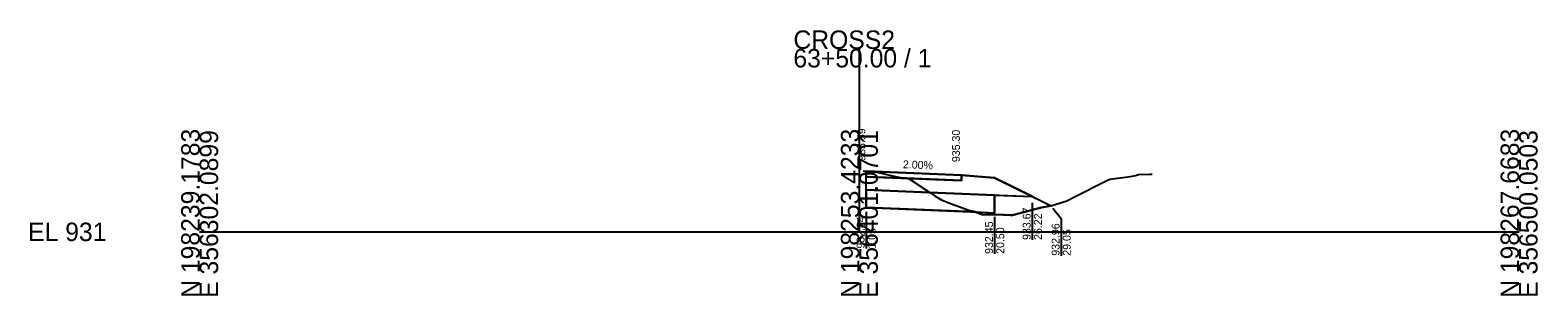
# Model space of a CAD drawing. Extents: x -26 to 203, y -10 to 14021.
# Drawn here: x -25.7 to 202.8, y 4490.3 to 4530.5 of the extents above; entities that cross this region are included whole.
import ezdxf

# ---------------------------------------------------------------- set-up
doc = ezdxf.new("R2010")
doc.units = 0
for name, color, linetype in [('Default', 7, 'Continuous'), ('P_E_XS_Ground', 7, 'Continuous'), ('P_XS', 7, 'Continuous'), ('P_XS_EAR_CommonGrnd', 7, 'Continuous'), ('P_XS_Lane', 7, 'Continuous'), ('P_XS_Rock', 7, 'Continuous')]:
    doc.layers.add(name, color=color, linetype=linetype)

msp = doc.modelspace()

# ---------------------------------------------------------------- linework, layer by layer
at = {"layer": 'Default'}
for p, q in [((100, 4500), (100, 4527.7)), ((0, 4500), (100, 4500)), ((100, 4500), (200, 4500))]:
    msp.add_line(p, q, dxfattribs=at)
at = {"layer": 'P_E_XS_Ground'}
for p, q in [((100.58, 4509.23), (101.11, 4509.18)), ((101.11, 4509.18), (102.72, 4509.05)), ((102.72, 4509.05), (103.3, 4508.9)), ((103.3, 4508.9), (105.48, 4508.36)), ((105.48, 4508.36), (106.22, 4508.22)), ((106.22, 4508.22), (107.55, 4508.04)), ((107.55, 4508.04), (111.49, 4505.42)), ((132.83, 4505.39), (137.43, 4507.73)), ((137.43, 4507.73), (137.97, 4507.97)), ((137.97, 4507.97), (141.08, 4508.39)), ((141.08, 4508.39), (141.87, 4508.55)), ((141.87, 4508.55), (142.32, 4508.66)), ((142.32, 4508.66), (143.99, 4508.71)), ((143.99, 4508.71), (144.38, 4508.72)), ((111.49, 4505.42), (112.45, 4504.87)), ((112.45, 4504.87), (113.82, 4504.27)), ((129.04, 4503.93), (131.46, 4504.68)), ((131.46, 4504.68), (132.83, 4505.39)), ((113.82, 4504.27), (116.74, 4503.24)), ((116.74, 4503.24), (117.08, 4503.18)), ((117.08, 4503.18), (118.78, 4502.58)), ((118.78, 4502.58), (120.76, 4502.63)), ((120.76, 4502.63), (122.91, 4502.51)), ((122.91, 4502.51), (123.23, 4502.51)), ((123.23, 4502.51), (127.61, 4503.69)), ((127.61, 4503.69), (129.04, 4503.93))]:
    msp.add_line(p, q, dxfattribs=at)
at = {"layer": 'P_XS'}
for p, q in [((101.05, 4509.18), (101.05, 4508.35)), ((101.05, 4508.35), (115.5, 4507.77)), ((101.05, 4506.35), (101.05, 4508.35)), ((115.5, 4508.6), (115.5, 4507.77)), ((101.05, 4506.35), (126.22, 4505.34)), ((101.05, 4506.35), (101.05, 4503.68)), ((120.5, 4505.57), (120.5, 4502.9)), ((101.05, 4503.68), (120.5, 4502.9))]:
    msp.add_line(p, q, dxfattribs=at)
at = {"layer": 'P_XS_EAR_CommonGrnd'}
for points in [[(103.3, 4508.9), (105.48, 4508.36), (106.22, 4508.22), (107.07, 4508.11), (115.5, 4507.77), (115.5, 4508.6), (101.05, 4509.18), (101.11, 4509.18), (102.72, 4509.05)], [(103.3, 4508.9), (105.48, 4508.36), (106.22, 4508.22), (107.07, 4508.11), (101.05, 4508.35), (101.05, 4509.18), (101.11, 4509.18), (102.72, 4509.05)], [(101.05, 4506.35), (101.05, 4508.35), (107.07, 4508.11), (107.55, 4508.04), (110.68, 4505.96)], [(107.55, 4508.04), (110.68, 4505.96), (120.5, 4505.57), (126.22, 4505.34), (120.5, 4508.2), (115.5, 4508.6), (115.5, 4507.77), (107.07, 4508.11)], [(113.82, 4504.27), (116.74, 4503.24), (117.08, 4503.18), (117.53, 4503.02), (101.05, 4503.68), (101.05, 4506.35), (110.68, 4505.96), (111.49, 4505.42), (112.45, 4504.87)], [(113.82, 4504.27), (116.74, 4503.24), (117.08, 4503.18), (117.53, 4503.02), (120.5, 4502.9), (120.5, 4505.57), (110.68, 4505.96), (111.49, 4505.42), (112.45, 4504.87)], [(126.22, 4505.34), (129.05, 4503.93), (127.61, 4503.69), (123.23, 4502.51), (122.91, 4502.51), (120.76, 4502.63), (118.78, 4502.58), (117.53, 4503.02), (120.5, 4502.9), (120.5, 4505.57)]]:
    msp.add_lwpolyline(points, close=True, dxfattribs=at)
at = {"layer": 'P_XS_Lane'}
for p, q in [((101.05, 4509.18), (115.5, 4508.6)), ((115.5, 4508.6), (120.5, 4508.2)), ((120.5, 4508.2), (129.05, 4503.93))]:
    msp.add_line(p, q, dxfattribs=at)
at = {"layer": 'P_XS_Rock'}
for p, q in [((101.03, 4503.05), (101.03, 4497.45)), ((120.5, 4502.26), (120.5, 4496.66)), ((126.21, 4504.37), (126.21, 4498.77)), ((129.32, 4503.6), (130.59, 4502)), ((130.59, 4502), (130.59, 4496.38))]:
    msp.add_line(p, q, dxfattribs=at)

# ---------------------------------------------------------------- texts
at = {"layer": 'Default'}
for s, p in [('CROSS2', (90, 4527.7)), ('63+50.00 / 1', (90, 4524.9)), ('EL 931', (-26, 4498.6))]:
    msp.add_text(s, height=2.8, dxfattribs=at).set_placement(p)
for s, p in [('N 198239.1783', (0, 4490)), ('E 356302.0899', (2.8, 4490)), ('N 198253.4233', (100, 4490)), ('E 356401.0701', (102.8, 4490)), ('N 198267.6683', (200, 4490)), ('E 356500.0503', (202.8, 4490))]:
    msp.add_text(s, height=2.8, rotation=90, dxfattribs=at).set_placement(p)
at = {"layer": 'P_XS_Rock'}
for s, rotation, p in [('935.59', 90, (100.91, 4510.76)), ('935.30', 90, (115.24, 4510.56)), ('2.00%', 357.7094, (106.58, 4509.64)), ('932.84', 90, (100.78, 4497.45)), ('933.67', 90, (125.96, 4498.77)), ('26.22', 90, (127.66, 4498.77)), ('1.05', 90, (102.48, 4497.45)), ('932.45', 90, (120.25, 4496.66)), ('20.50', 90, (121.95, 4496.66)), ('932.96', 90, (130.34, 4496.38)), ('29.05', 90, (132.04, 4496.38))]:
    msp.add_text(s, height=1.2, rotation=rotation, dxfattribs=at).set_placement(p)

doc.saveas('drawing.dxf')
